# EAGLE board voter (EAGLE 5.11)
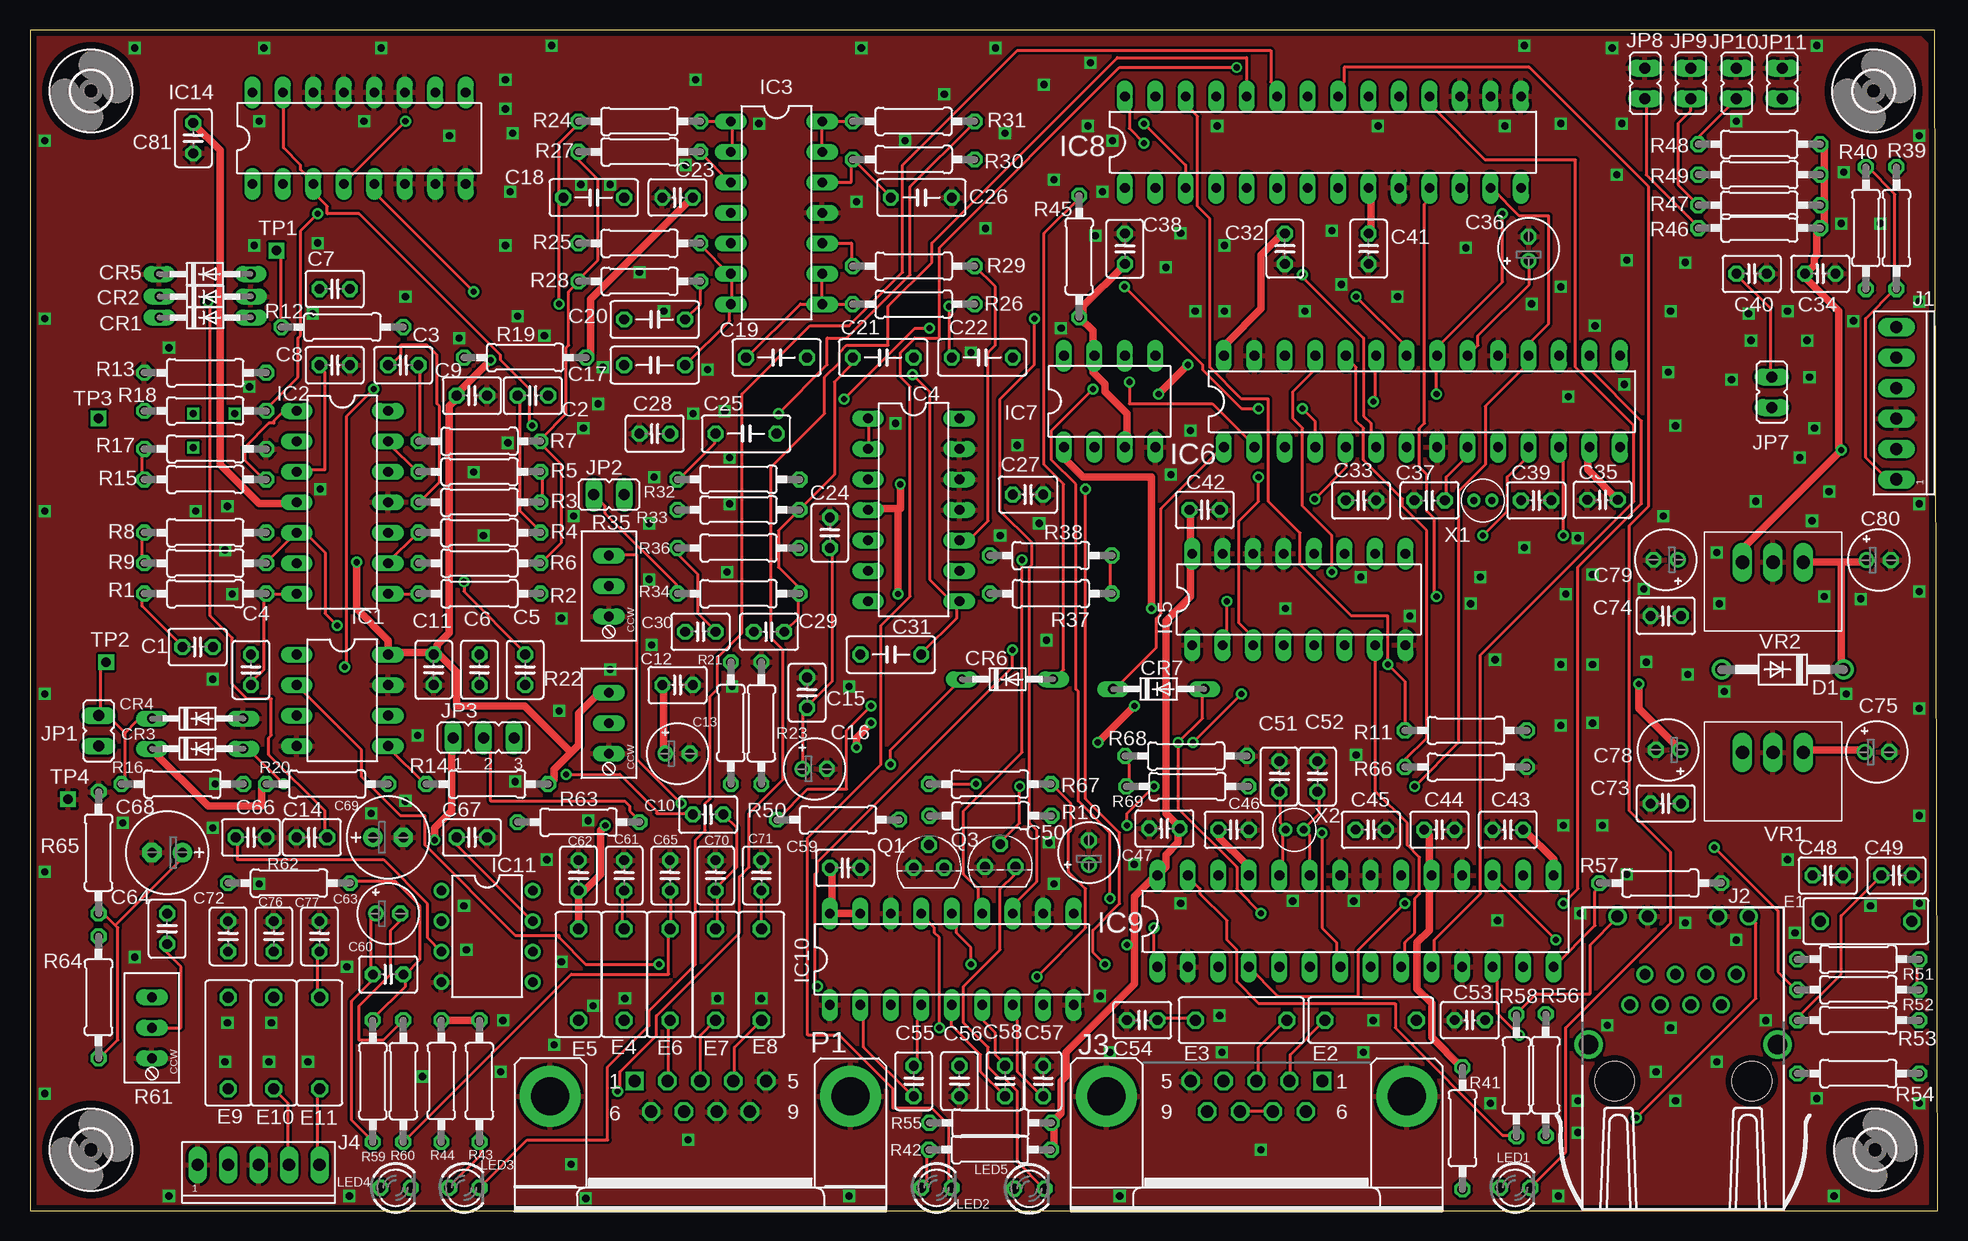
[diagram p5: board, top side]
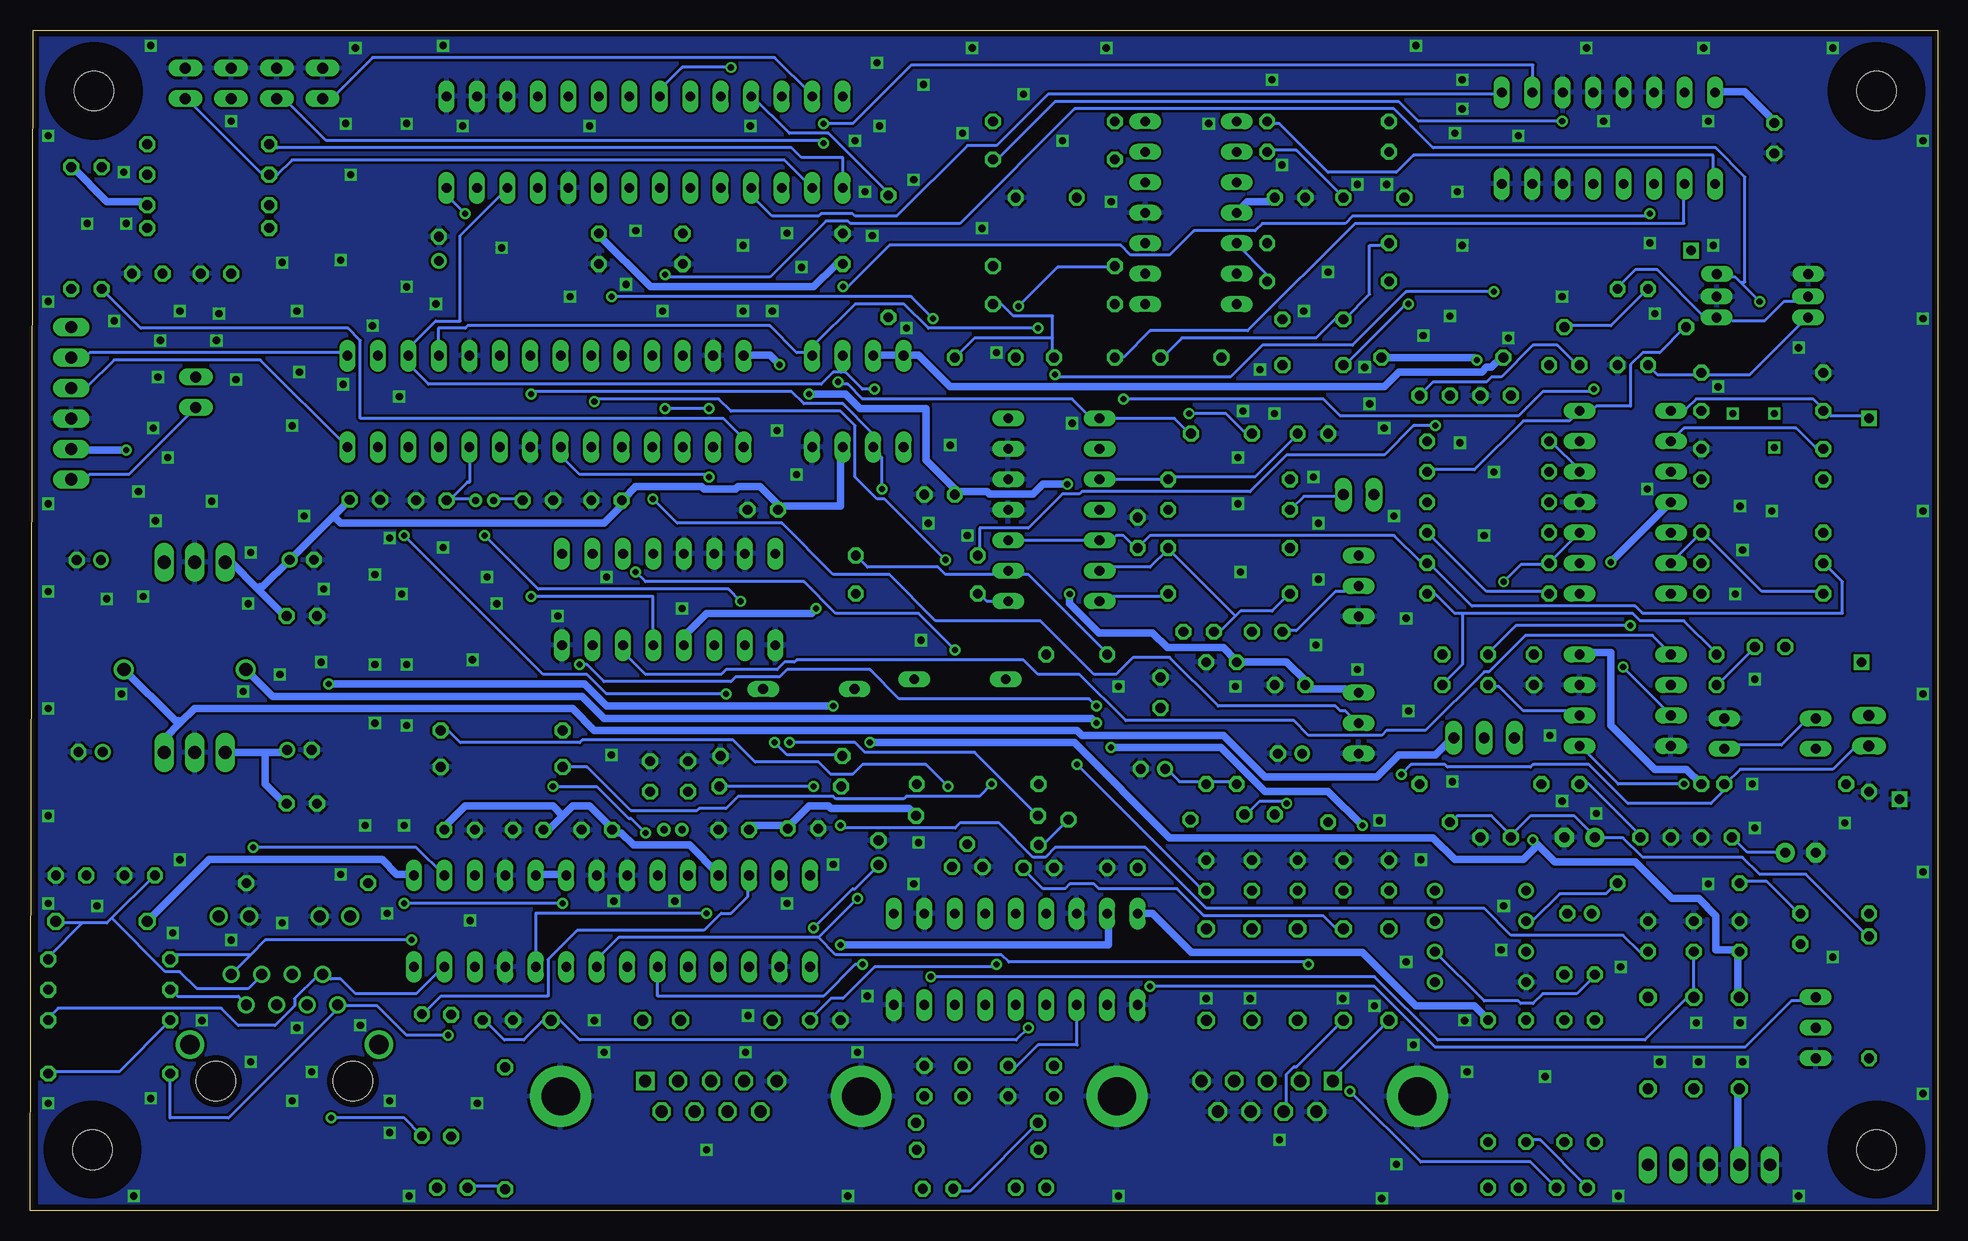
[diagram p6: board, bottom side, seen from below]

Size 159 x 98.44 mm. Coordinates in mm from the lower left corner, seen from the top.
Outline: 0,0.02 159,0 158.75,98.44 0,98.44 0,0.02
Copper layers (1*16): Top 0.035mm / dielectric 1.5mm / Bottom 0.035mm
Design rules "default *": minimum track width 10mil, minimum drill 20mil, track to track 8mil, track to pad 8mil, pad to pad 8mil, via to via 8mil, smd to smd 8mil, copper to edge 20mil, drill to drill 8mil, minimum pad ring 10mil, minimum via ring 8mil, stop-mask expansion 4mil, vias tented up to drill 0mil, thermal gap 10mil
Net classes: 0 default: width 0.203 mm, drill 0.508 mm, clearance 0.203 mm; 1 power: width 0.635 mm, drill 0.508 mm, clearance 0.203 mm

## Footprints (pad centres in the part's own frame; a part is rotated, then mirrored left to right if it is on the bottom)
C025-030X050 = drill 0.813 octagon: 1 -1.27,0; 2 1.27,0
E2-5 = drill 0.813 pad 1.27 round: + -1.016,0 | drill 0.813 pad 1.27 octagon: - 1.016,0
C050-030X075 = drill 0.813 octagon: 1 -2.54,0; 2 2.54,0
E2,5-7 = drill 0.813 pad 1.6 round: + -1.27,0 | drill 0.813 pad 1.6 octagon: - 1.27,0
DO34-7 = drill 0.813 long: A 3.81,0; C -3.81,0
DO41-10 = drill 1.118 round: A 5.08,0; C -5.08,0
FBONLEADSSMALL = drill 0.914 octagon: 1 -3.81,0; 2 3.81,0
DIL08 = drill 0.813 long: 1 -3.81,-3.81; 2 -1.27,-3.81; 3 1.27,-3.81; 4 3.81,-3.81; 5 3.81,3.81; 6 1.27,3.81; 7 -1.27,3.81; 8 -3.81,3.81
DIL14 = drill 0.813 long: 1 -7.62,-3.81; 2 -5.08,-3.81; 3 -2.54,-3.81; 4 0,-3.81; 5 2.54,-3.81; 6 5.08,-3.81; 7 7.62,-3.81; 8 7.62,3.81; 9 5.08,3.81; 10 2.54,3.81; 11 0,3.81; 12 -2.54,3.81; 13 -5.08,3.81; 14 -7.62,3.81
DIL16 = drill 0.813 long: 1 -8.89,-3.81; 2 -6.35,-3.81; 3 -3.81,-3.81; 4 -1.27,-3.81; 5 1.27,-3.81; 6 3.81,-3.81; 7 6.35,-3.81; 8 8.89,-3.81; 9 8.89,3.81; 10 6.35,3.81; 11 3.81,3.81; 12 1.27,3.81; 13 -1.27,3.81; 14 -3.81,3.81; 15 -6.35,3.81; 16 -8.89,3.81
DIL28-3 = drill 0.813 long: 1 -16.51,-2.54; 2 -13.97,-2.54; 3 -11.43,-2.54; 4 -8.89,-2.54; 5 -6.35,-2.54; 6 -3.81,-2.54; 7 -1.27,-2.54; 8 1.27,-2.54; 9 3.81,-2.54; 10 6.35,-2.54; 11 8.89,-2.54; 12 11.43,-2.54; 13 13.97,-2.54; 14 16.51,-2.54; 15 16.51,5.08; 16 13.97,5.08; 17 11.43,5.08; 18 8.89,5.08; 19 6.35,5.08; 20 3.81,5.08; 21 1.27,5.08; 22 -1.27,5.08; 23 -3.81,5.08; 24 -6.35,5.08; 25 -8.89,5.08; 26 -11.43,5.08; 27 -13.97,5.08; 28 -16.51,5.08
DIL28-3' = drill 0.813 long: 1 -16.51,-3.81; 2 -13.97,-3.81; 3 -11.43,-3.81; 4 -8.89,-3.81; 5 -6.35,-3.81; 6 -3.81,-3.81; 7 -1.27,-3.81; 8 1.27,-3.81; 9 3.81,-3.81; 10 6.35,-3.81; 11 8.89,-3.81; 12 11.43,-3.81; 13 13.97,-3.81; 14 16.51,-3.81; 15 16.51,3.81; 16 13.97,3.81; 17 11.43,3.81; 18 8.89,3.81; 19 6.35,3.81; 20 3.81,3.81; 21 1.27,3.81; 22 -1.27,3.81; 23 -3.81,3.81; 24 -6.35,3.81; 25 -8.89,3.81; 26 -11.43,3.81; 27 -13.97,3.81; 28 -16.51,3.81
DIL18 = drill 0.813 long: 1 -10.16,-3.81; 2 -7.62,-3.81; 3 -5.08,-3.81; 4 -2.54,-3.81; 5 0,-3.81; 6 2.54,-3.81; 7 5.08,-3.81; 8 7.62,-3.81; 9 10.16,-3.81; 10 10.16,3.81; 11 7.62,3.81; 12 5.08,3.81; 13 2.54,3.81; 14 0,3.81; 15 -2.54,3.81; 16 -5.08,3.81; 17 -7.62,3.81; 18 -10.16,3.81
DIL08' = drill 0.813 pad 1.27 round: 1 -3.81,-3.81; 2 -1.27,-3.81; 3 1.27,-3.81; 4 3.81,-3.81; 5 3.81,3.81; 6 1.27,3.81; 7 -1.27,3.81; 8 -3.81,3.81
MTA6-100 = drill 1.016 long: 1 5.08,0; 2 2.54,0; 3 0,0; 4 -2.54,0; 5 -5.08,0; 6 -7.62,0
J1 = drill 0.9 pad 1.3 round: 1 4.445,2.54; 2 3.175,0; 3 1.905,2.54; 4 0.635,0; 5 -0.635,2.54; 6 -1.905,0; 7 -3.175,2.54; 8 -4.445,0 | drill 1 pad 1.422 round: 9 5.465,7.37; 10 2.925,7.37; 11 -2.925,7.37; 12 -5.465,7.37 | drill 1.6 pad 2.184 round: M1 -7.875,-3.3; M2 7.875,-3.3 | hole 3.3: 5.715,-6.35; -5.715,-6.35
DSUB9F = drill 1.016 square: 1 -5.486,0 | drill 1.016 octagon: 2 -2.743,0; 3 0,0; 4 2.743,0; 5 5.486,0; 6 -4.115,2.54; 7 -1.372,2.54; 8 1.372,2.54; 9 4.115,2.54 | drill 3.175 pad 5.08 round: SHELL1 -12.522,1.27; SHELL2 12.522,1.27
MTA5-100 = drill 1.016 long: 1 5.08,0; 2 2.54,0; 3 0,0; 4 -2.54,0; 5 -5.08,0
JP1 = drill 0.914 long: 1 0,-1.27; 2 0,1.27
JP2 = drill 0.914 long: 1 -2.54,0; 2 0,0; 3 2.54,0
LED3MM = drill 0.813 octagon: A -1.27,0; K 1.27,0
DSUB9M = drill 1.016 square: 1 -5.486,0 | drill 1.016 octagon: 2 -2.743,0; 3 0,0; 4 2.743,0; 5 5.486,0; 6 -4.115,-2.54; 7 -1.372,-2.54; 8 1.372,-2.54; 9 4.115,-2.54 | drill 3.175 pad 5.08 round: G1 -12.522,-1.27; G2 12.522,-1.27
TO92 = drill 0.813 octagon: 1 1.27,0; 2 0,1.905; 3 -1.27,0
0207/10 = drill 0.813 octagon: 1 -5.08,0; 2 5.08,0
BOURNS3296 = drill 0.813 long: 1 2.54,0; 2 0,0; 3 -2.54,0
TESTPIN = drill 0.8 square: TP 0,0
3,3 = hole 3.3: 0,0
R-78XX = drill 1.092 long: 1 -2.54,0; 2 0,0; 3 2.54,0
TUNINGFORKXTAL = drill 0.6 round: 1 -0.75,0; 2 0.75,0

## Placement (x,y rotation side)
C1  47p  [C025-030X050]  13.97,47.01 0 top
C2  1000p  [C025-030X050]  41.91,67.96 0 top
C3  1000p  [C025-030X050]  31.11,70.5 0 top
C4  1000p  [C025-030X050]  18.41,45.11 90 top
C5  1000p  [C025-030X050]  41.27,45.11 90 top
C6  330p  [C025-030X050]  37.47,45.11 270 top
C7  0.1u  [C025-030X050]  25.4,76.85 0 top
C8  0.1u  [C025-030X050]  25.4,70.5 0 top
C9  0.1u  [C025-030X050]  36.83,67.96 0 top
C10  0.1u  [C025-030X050]  56.52,33.04 0 top
C11  0.1u  [C025-030X050]  33.66,45.11 270 top
C12  0.1u  [C025-030X050]  53.98,43.84 0 top
C13  22u  [E2-5]  53.98,38.12 0 top
C14  0.1u  [C025-030X050]  23.5,31.13 180 top
C15  0.1u  [C025-030X050]  64.77,43.2 90 top
C16  22u  [E2-5]  65.41,36.85 0 top
C17  0.068u  [C050-030X075]  52.07,70.5 180 top
C18  0.068u  [C050-030X075]  46.99,84.47 0 top
C19  0.068u  [C050-030X075]  62.23,71.14 0 top
C20  0.068u  [C050-030X075]  52.07,74.31 0 top
C21  0.068u  [C050-030X075]  71.12,71.14 0 top
C22  0.068u  [C050-030X075]  79.38,71.14 180 top
C23  0.1u  [C025-030X050]  53.98,84.47 180 top
C24  0.1u  [C025-030X050]  66.67,56.54 90 top
C25  0.015u  [C050-030X075]  59.69,64.79 0 top
C26  6800p  [C050-030X075]  74.3,84.47 0 top
C27  0.1u  [C025-030X050]  83.19,59.71 0 top
C28  1000p  [C025-030X050]  52.07,64.79 180 top
C29  22p  [C025-030X050]  61.59,48.28 180 top
C30  0.1u  [C025-030X050]  55.88,48.28 0 top
C31  4700p  [C050-030X075]  71.75,46.38 0 top
C32  0.1u  [C025-030X050]  104.6,80.21 270 top
C33  0.1u  [C025-030X050]  110.95,59.23 0 top
C34  0.1u  [C025-030X050]  149.22,78.12 0 top
C35  0.1u  [C025-030X050]  131.09,59.28 180 top
C36  10u  [E2-5]  124.92,80.21 90 top
C37  22p  [C025-030X050]  116.66,59.23 180 top
C38  0.1u  [C025-030X050]  91.26,80.21 90 top
C39  22p  [C025-030X050]  125.55,59.23 0 top
C40  0.22u  [C025-030X050]  143.51,78.12 0 top
C41  0.1u  [C025-030X050]  111.58,80.21 270 top
C42  0.1u  [C025-030X050]  97.92,58.44 0 top
C43  0.1u  [C025-030X050]  123.19,31.77 180 top
C44  0.1u  [C025-030X050]  117.47,31.77 0 top
C45  0.1u  [C025-030X050]  111.76,31.77 0 top
C46  0.1u  [C025-030X050]  100.33,31.77 0 top
C47  0.1u  [C025-030X050]  94.56,31.87 180 top
C48  0.1u  [C025-030X050]  149.86,27.96 0 top
C49  0.1u  [C025-030X050]  155.57,27.96 0 top
C50  10u  [E2-5]  88.27,29.86 90 top
C51  22p  [C025-030X050]  104.14,36.22 90 top
C52  22p  [C025-030X050]  107.31,36.22 90 top
C53  47p  [C025-030X050]  120.02,15.89 180 top
C54  47p  [C025-030X050]  92.71,15.89 180 top
C55  0.1u  [C025-030X050]  73.66,10.81 90 top
C56  0.1u  [C025-030X050]  77.47,10.81 270 top
C57  0.1u  [C025-030X050]  84.45,10.81 90 top
C58  0.1u  [C025-030X050]  81.28,10.81 90 top
C59  0.1u  [C025-030X050]  67.94,28.59 0 top
C60  47p  [C025-030X050]  29.84,19.7 0 top
C61  47p  [C025-030X050]  49.53,27.96 90 top
C62  47p  [C025-030X050]  45.72,27.96 90 top
C63  10u NP  [E2-5]  29.84,24.79 0 top
C64  0.47u  [C025-030X050]  11.43,23.52 270 top
C65  47p  [C025-030X050]  53.34,27.96 90 top
C66  0.1u  [C025-030X050]  18.41,31.13 0 top
C67  0.1u  [C025-030X050]  36.83,31.13 0 top
C68  100u  [E2,5-7]  11.43,29.86 180 top
C69  100u  [E2,5-7]  29.84,31.13 0 top
C70  47p  [C025-030X050]  57.15,27.96 90 top
C71  47p  [C025-030X050]  60.96,27.96 90 top
C72  47p  [C025-030X050]  16.51,22.88 90 top
C73  0.1u  [C025-030X050]  136.35,33.95 180 top
C74  0.1u  [C025-030X050]  136.35,49.6 180 top
C75  4.7u  [E2-5]  153.95,38.25 0 top
C76  47p  [C025-030X050]  20.32,22.88 90 top
C77  47p  [C025-030X050]  24.13,22.88 90 top
C78  1.0u  [E2-5]  136.55,38.42 180 top
C79  1.0u  [E2-5]  136.35,54.27 180 top
C80  4.7u  [E2-5]  154.1,54.25 0 top
C81  0.1u  [C025-030X050]  13.61,89.43 90 top
CR1  BAT85  [DO34-7]  14.61,74.47 0 top
CR2  BAT85  [DO34-7]  14.61,76.22 0 top
CR3  BAT85  [DO34-7]  13.97,38.53 0 top
CR4  BAT85  [DO34-7]  13.97,41.04 0 top
CR5  BAT85  [DO34-7]  14.58,78.1 0 top
CR6  BAT85  [DO34-7]  81.48,44.32 0 top
CR7  BAT85  [DO34-7]  94.08,43.5 0 top
D1  1N5819  [DO41-10]  146.1,45.13 180 top
E1  FBONLDSM  [FBONLEADSSMALL]  153.03,24.15 180 top
E2  FBONLDSM  [FBONLEADSSMALL]  111.76,15.89 180 top
E3  FBONLDSM  [FBONLEADSSMALL]  100.97,15.89 0 top
E4  FBONLDSM  [FBONLEADSSMALL]  49.53,19.7 90 top
E5  FBONLDSM  [FBONLEADSSMALL]  45.72,19.7 90 top
E6  FBONLDSM  [FBONLEADSSMALL]  53.34,19.7 90 top
E7  FBONLDSM  [FBONLEADSSMALL]  57.15,19.7 90 top
E8  FBONLDSM  [FBONLEADSSMALL]  60.96,19.7 90 top
E9  FBONLDSM  [FBONLEADSSMALL]  16.51,13.99 270 top
E10  FBONLDSM  [FBONLEADSSMALL]  20.32,13.99 270 top
E11  FBONLDSM  [FBONLEADSSMALL]  24.13,13.99 270 top
IC1  MCP4131  [DIL08]  26.04,42.57 270 top
IC2  MCP6004P  [DIL14]  26.04,59.08 270 top
IC3  MCP6004P  [DIL14]  62.23,83.2 270 top
IC4  MCP6004P  [DIL14]  73.66,58.44 270 top
IC5  74HC139N  [DIL16]  105.77,50.97 0 top
IC6  DSPIC33FJ128GP802  [DIL28-3]  116.03,66.21 0 top
IC7  25LC080  [DIL08]  89.99,67.48 0 top
IC8  MCP23S17SP  [DIL28-3']  107.77,89.1 0 top
IC9  ENC28J60SP  [DIL28-3']  110.49,24.15 0 top
IC10  MAX3222  [DIL18]  76.83,20.97 0 top
IC11  AD820AN  [DIL08']  38.1,22.88 270 top
IC14  74HC4053N  [DIL16]  27.43,89.43 0 top
J1  [MTA6-100]  155.57,66.06 270 top
J2  J1011F01P  [J1]  137.79,17.16 0 top
J3  DB9FRASFLUSH  [DSUB9F]  102.23,10.81 180 top
J4  [MTA5-100]  19.05,3.83 180 top
JP1  [JP1]  5.71,40.03 0 top
JP2  [JP1]  48.26,59.71 270 top
JP3  [JP2]  37.8,39.44 0 top
JP7  [JP1]  145.19,68.24 0 top
JP8  [JP1]  134.62,94 0 top
JP9  [JP1]  138.43,94 0 top
JP10  [JP1]  142.24,94 0 top
JP11  [JP1]  146.05,94 0 top
LED1  [LED3MM]  123.8,1.93 0 top
LED2  [LED3MM]  75.56,1.93 0 top
LED3  [LED3MM]  36.2,1.93 0 top
LED4  [LED3MM]  30.48,1.93 0 top
LED5  [LED3MM]  83.31,1.85 0 top
P1  DB9MRASFLUSH  [DSUB9M]  55.88,10.81 0 top
Q1  2N4401  [TO92]  74.93,28.59 0 top
Q3  2N4401  [TO92]  80.87,28.67 0 top
R1  220K  [0207/10]  14.61,51.46 0 top
R2  7.32K  [0207/10]  37.47,51.46 180 top
R3  3.01K  [0207/10]  37.47,59.08 0 top
R4  1K  [0207/10]  37.47,56.54 0 top
R5  1K  [0207/10]  37.47,61.62 0 top
R6  17.8K  [0207/10]  37.47,54 180 top
R7  154K  [0207/10]  37.47,64.16 180 top
R8  10K  [0207/10]  14.61,56.54 0 top
R9  220K  [0207/10]  14.61,54 0 top
R10  10K  [0207/10]  80.06,32.94 0 top
R11  4.7K  [0207/10]  119.68,40.05 180 top
R12  220  [0207/10]  26.04,73.68 0 top
R13  22K  [0207/10]  14.61,69.87 0 top
R14  100K  [0207/10]  38.1,35.58 0 top
R15  33K  [0207/10]  14.61,60.98 0 top
R16  100K  [0207/10]  12.7,35.58 0 top
R17  10K  [0207/10]  14.61,63.52 0 top
R18  220  [0207/10]  14.61,66.69 0 top
R19  4.7  [0207/10]  41.27,71.14 0 top
R20  10K  [0207/10]  24.77,35.58 180 top
R21  2.2K  [0207/10]  58.42,40.66 90 top
R22  10K  [BOURNS3296]  48.26,40.66 270 top
R23  2.2K  [0207/10]  60.96,40.66 270 top
R24  3.01K  [0207/10]  50.8,90.83 0 top
R25  8.25K  [0207/10]  50.8,80.66 0 top
R26  11.0K  [0207/10]  73.66,75.58 180 top
R27  47.5K  [0207/10]  50.8,88.28 0 top
R28  16.2K  [0207/10]  50.8,77.49 0 top
R29  12.1K  [0207/10]  73.66,78.76 180 top
R30  12,4K  [0207/10]  73.66,87.65 180 top
R31  7.68K  [0207/10]  73.66,90.83 0 top
R32  21.5K  [0207/10]  59.05,60.98 0 top
R33  110K  [0207/10]  59.05,58.44 0 top
R34  1.0M  [0207/10]  59.05,51.46 0 top
R35  100K  [BOURNS3296]  48.26,52.09 270 top
R36  100K  [0207/10]  59.05,55.27 0 top
R37  100K  [0207/10]  85.09,51.46 180 top
R38  33K  [0207/10]  85.09,54.63 0 top
R39  10K  [0207/10]  155.57,81.94 90 top
R40  360  [0207/10]  153.03,81.94 90 top
R41  180  [0207/10]  119.41,6.88 90 top
R42  180  [0207/10]  80.01,5.1 0 top
R43  180  [0207/10]  37.47,10.81 90 top
R44  180  [0207/10]  34.29,10.81 90 top
R45  10K  [0207/10]  87.45,79.57 270 top
R46  10K  [0207/10]  144.15,81.94 0 top
R47  10K  [0207/10]  144.15,83.84 0 top
R48  10K  [0207/10]  144.15,88.92 0 top
R49  10K  [0207/10]  144.15,86.38 0 top
R50  4.7K  [0207/10]  67.36,32.61 0 top
R51  49.9  [0207/10]  152.4,20.97 180 top
R52  49.9  [0207/10]  152.4,18.43 0 top
R53  49.9  [0207/10]  152.4,15.89 0 top
R54  49.9  [0207/10]  152.4,11.45 0 top
R55  180  [0207/10]  80.06,7.34 0 top
R56  180  [0207/10]  126.34,11.32 270 top
R57  2.32K  [0207/10]  135.89,27.32 180 top
R58  180  [0207/10]  123.9,11.27 90 top
R59  330K  [0207/10]  28.57,10.81 270 top
R60  33  [0207/10]  31.11,10.81 270 top
R61  10K  [BOURNS3296]  10.16,15.26 270 top
R62  10K  [0207/10]  21.59,27.32 0 top
R63  4.7  [0207/10]  45.72,32.41 0 top
R64  10K  [0207/10]  5.71,17.8 90 top
R65  10K  [0207/10]  5.71,29.86 270 top
R66  10K  [0207/10]  119.68,37 180 top
R67  4.7K  [0207/10]  80.01,35.58 0 top
R68  10K  [0207/10]  96.37,37.92 180 top
R69  4.7K  [0207/10]  96.47,35.38 0 top
TP1  TESTPINTPSQ025  [TESTPIN]  20.55,80.06 0 top
TP2  TESTPINTPSQ025  [TESTPIN]  6.35,45.74 0 top
TP3  TESTPINTPSQ025  [TESTPIN]  5.71,66.06 0 top
TP4  TESTPINTPSQ025  [TESTPIN]  3.17,34.31 0 top
U$21  [3,3]  5.08,93.36 0 top
U$22  [3,3]  5.08,5.1 0 top
U$23  [3,3]  153.8,5.1 0 top
U$24  [3,3]  153.67,93.36 0 top
VR1  R785_0-0_5  [R-78XX]  145.29,38.22 180 top
VR2  R783_3-0_5  [R-78XX]  145.29,54.07 180 top
X1  9.60MHz  [TUNINGFORKXTAL]  121.11,59.23 180 top
X2  25.0MHz  [TUNINGFORKXTAL]  105.41,31.77 0 top

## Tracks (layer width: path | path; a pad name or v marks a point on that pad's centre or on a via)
!CS_EEPROM  (via drill 0.51)
  Top 0.635: v93.47,50.21 93.47,61.18 87.78,61.18 86.36,62.61 86.36,63.62 IC7.1
  Bottom 0.635: v93.47,50.21 93.88,49.8 102.62,49.8 104.44,47.98 104.44,47.16 IC5.4
!CS_ETHER
  Top 0.254: IC9.9 114.4,20.34 114.61,20.54 114.61,22.37 115.42,23.18 115.42,26.03 115.82,26.44 115.82,29.48 114.81,30.5 114.81,32.33 112.17,34.97 112.17,47.16 IC5.7
!CS_IOEXP  (via drill 0.51)
  Top 0.254: v117.25,51.23 117.04,51.43 117.04,57.73 116.43,58.34 116.43,61.39 115.82,62 115.82,65.25 116.23,65.65 116.23,83.94 116.64,84.35 116.64,85.16 IC8.11
  Bottom 0.254: v117.25,51.23 107.09,51.23 107.09,47.16 IC5.5
!CS_POT
  Bottom 0.254: IC1.1 22.35,46.55 23.77,47.98 34.34,47.98 37.39,44.93 37.8,44.93 42.67,40.05 45.92,40.05 46.33,39.64 52.43,39.64 53.65,40.86 67.67,40.86 71.53,44.72 74.98,44.72 76.2,45.94 95.1,45.94 95.3,45.74 96.11,45.74 96.72,45.13 100.99,45.13 101.4,44.72 107.7,44.72 109.53,46.55 109.53,47.16 IC5.6
!CTCSS_IN  (via drill 0.51)
  Top 0.254: E8.2 C71.1 | v71.73,37.21 71.73,38.43 77.62,44.32 CR6.C
  Bottom 0.254: v71.73,37.21 61.37,26.84 60.96,26.84 C71.1
!INT_ETHER  (via drill 0.51)
  Top 0.254: IC9.4 104.04,17.9 110.74,17.9 110.74,21.76 v114.61,25.62 | v127.81,25.62 129.03,26.84 129.03,53.67 134.31,58.95 134.31,65.86 130.05,70.12 130.05,71.14 IC6.16
  Bottom 0.254: v114.61,25.62 v127.81,25.62
!MCLR
  Top 0.254: CR7.C 90.42,43.51 93.88,46.96 93.88,49.4 94.28,49.8 94.28,58.54 99.36,63.62 IC6.1
  Bottom 0.254: R40.1 149.76,73.58 132.49,73.58 131.47,72.56 131.47,66.06 101.19,66.06 99.57,64.43 99.57,63.83 IC6.1
!POT_CS  (via drill 0.51)
  Top 0.254: v99.77,50.82 99.77,47.37 99.57,47.16 IC5.2 | v121.11,56.31 123.14,58.34 123.14,61.18 124.77,62.81 124.77,63.62 IC6.11
  Bottom 0.254: v99.77,50.82 100.79,51.84 116.64,51.84 v121.11,56.31
!PRST
  Top 0.254: R40.2 153.21,86.99 155.45,84.75 155.45,77.03 R39.1 155.45,76.83 153.01,74.39 153.01,62.81 154.84,60.98 J1.1
  Bottom 0.254: JP7.1 150.77,61.39 154.03,61.39 154.43,60.98 J1.1
!RST  (via drill 0.51)
  Top 0.254: CR7.A 97.74,43.51 97.74,41.07 v95.71,39.03 95.71,33.55 100.58,28.67 100.58,26.84 v102.62,24.81 | IC9.10 117.04,20.54 117.04,22.57 120.9,26.44 120.9,46.35 133.71,59.15 133.71,65.45 128.83,70.33 128.83,87.6 121.31,87.6 117.04,91.87 117.04,92.68 116.84,92.88 IC8.18
  Bottom 0.254: R10.1 80.26,38.22 89.41,38.22 90.22,39.03 v95.71,39.03 | IC9.10 116.84,24.81 v102.62,24.81
+3.3V  (via drill 0.51)
  Top 0.635: 72.34,58.54 72.54,58.54 v72.54,60.57 | 72.34,58.54 69.9,58.54 IC4.4 | IC6.28 99.77,71.55 99.77,72.36 102.62,75.2 102.62,79.67 104.44,81.5 C32.1 | v94.08,68.09 v96.52,70.53 | v38.41,70.94 35.56,68.09 C9.1 35.56,67.69 34.95,67.08 34.95,48.18 33.93,47.16 33.93,46.96 C11.1 | C23.1 55.07,84.35 46.74,76.02 46.74,71.55 46.53,71.34 46.53,71.14 R19.2 | 45.11,38.22 45.72,38.83 45.72,41.47 47.35,43.1 48.16,43.1 R22.3 | 45.11,38.22 43.69,36.8 43.69,35.99 43.28,35.58 R14.2 | C13.+ 52.83,38.22 52.83,43.71 C12.1 | CR3.C 10.16,38.43 14.83,33.75 19.3,33.75 19.3,35.17 19.51,35.38 19.51,35.58 R20.2 | C11.1 33.53,46.55 29.87,46.55 IC1.8 29.87,46.76 29.87,47.57 27.23,50.21 v27.23,54.07 | C81.2 13.61,90.65 15.85,88.41 15.85,62.2 19.1,58.95 22.15,58.95 IC2.4 | 45.11,38.22 41.25,42.08 35.56,42.08 35.56,44.93 33.73,46.76 C11.1 | v72.34,51.43 72.34,58.54
  Bottom 0.635: v72.54,60.57 74.57,60.57 75.39,59.76 79.05,59.76 79.25,59.96 81.69,59.96 81.89,59.76 C27.1 81.89,60.17 84.33,62.61 84.33,66.87 89.81,66.87 91.03,68.09 v94.08,68.09 | v96.52,70.53 97.33,71.34 99.36,71.34 IC6.28 | IC3.4 58.32,83.33 57.51,84.14 55.68,84.14 55.47,84.35 55.27,84.35 C23.1 | v38.41,70.94 38.61,71.14 R19.2 | R22.3 48.36,43.3 49.17,43.3 49.38,43.51 52.43,43.51 52.63,43.71 C12.1 52.63,44.11 54.25,45.74 R21.2 58.52,45.94 59.54,46.96 64.21,46.96 65.43,48.18 69.9,48.18 72.34,50.62 v72.34,51.43 | C81.2 13.61,90.85 16.05,93.29 18.49,93.29 IC14.16 | v27.23,54.07 IC2.4 | R20.2 19.71,35.58 20.93,36.8 23.57,36.8 27.23,40.46 27.23,46.55 29.67,46.55 IC1.8
ASEL1  (via drill 0.51)
  Top 0.254: v92.86,90.65 96.32,87.19 96.32,85.36 IC8.3
  Bottom 0.254: v92.86,90.65 90.42,90.65 85.55,95.52 33.73,95.52 33.73,93.29 IC14.10
ASEL2
  Bottom 0.254: IC14.9 36.37,93.09 74.17,93.09 78.44,88.82 80.87,88.82 86.77,82.93 90.22,82.93 90.42,83.13 93.07,83.13 93.27,82.93 97.13,82.93 98.75,84.55 98.75,85.16 IC8.4
DAC  (via drill 0.51)
  Top 0.254: v65.63,18.71 65.43,18.92 65.43,28.06 65.63,28.27 65.63,29.08 81.89,45.33 v81.89,46.76 | v108.51,53.26 108.51,56.31 106.07,58.75 106.07,65.25 105.26,66.06 105.26,68.3 107.09,70.12 107.09,71.14 IC6.25
  Bottom 0.254: v65.63,18.71 46.94,18.71 41.86,13.63 16.05,13.63 12.19,17.5 10.36,17.5 10.16,17.7 R61.3 | v81.89,46.76 84.94,49.8 91.85,49.8 94.49,52.45 107.7,52.45 v108.51,53.26
FLTNOISE
  Top 0.254: TP1.TP 20.93,79.67 20.93,73.78 R12.1 | R3.2 42.67,59.15 42.67,61.59 R5.2
  Bottom 0.254: R5.2 42.47,61.79 38.61,61.79 34.54,65.86 30.68,65.86 IC2.14 29.67,66.67 28.85,66.67 28.45,67.08 25.6,67.08 25.6,70.53 24.59,71.55 23.16,71.55 21.13,73.58 R12.1
GND  (via drill 0.6)
  other vias: 157.48,32.94 157.48,41.88 1.22,89.22 1.22,74.39 1.22,9.77 1.22,28.26 1.22,58.34 1.22,43.1 11.58,1.24 26.62,1.24 46.33,1.04 68.28,1.24 90.83,1.24 111.96,15.87 127.41,1.24 150.37,1.24 157.48,8.96 157.48,25.62 157.48,51.63 157.48,58.95 157.48,75.81 157.48,89.63 148.95,97.15 131.88,96.95 124.56,97.15 88.39,95.73 80.47,96.95 84.53,93.9 69.29,96.95 43.48,97.15 29.26,96.95 19.51,96.95 8.74,96.95 19.1,90.85 34.95,89.63 39.62,91.87 39.62,94.3 40.03,84.96 39.62,80.49 31.29,76.22 40.64,74.59 35.76,72.77 18.29,68.7 7.72,32.33 24.18,60.17 15.24,31.92 32.31,39.64 31.29,34.16 36.17,25.42 36.37,21.76 26.42,20.34 19.1,27.25 16.46,15.67 20.12,15.67 23.16,12.42 19.91,12.42 16.26,12.42 39.42,15.87 32.72,11.2 8.74,21.15 49.58,17.7 57.3,17.7 43.08,29.28 46.53,32.53 44.09,41.68 40.44,35.78 44.3,49.4 37.8,56.31 45.31,57.93 36.98,61.59 39.83,64.03 46.13,65.25 47.35,67.28 52.02,61.18 51.61,57.32 58.32,58.95 58.32,62.81 57.91,66.67 56.49,70.12 47.75,70.33 42.88,72.97 50.8,78.25 48.36,85.57 45.92,85.57 55.47,94.3 60.76,90.65 54.66,87.19 68.88,84.14 79.65,81.91 72.95,89.22 76.2,93.09 81.28,89.83 78.44,71.55 85.95,73.58 131.47,15.46 72.14,65.65 82.3,63.82 122.33,24.2 127.81,32.13 131.06,32.13 135.53,11.6 137.16,9.16 129.03,9.16 129.03,6.52 121.72,8.96 140.61,12.42 148.95,9.37 144.68,15.87 147.12,23.18 153.42,25.42 133.1,28.06 146.51,29.28 130.25,40.66 127.61,40.46 130.25,45.54 127.61,45.54 134.72,45.74 138.18,44.72 141.22,43.3 151.38,43.1 152.6,51.02 149.56,51.23 140.82,50.62 140.61,54.88 148.54,57.53 143.87,59.15 141.83,69.31 148.34,69.51 148.13,72.56 143.46,72.56 143.26,74.8 146.51,75 151.99,74.19 150.98,82.32 154.23,82.32 151.18,86.58 137.97,79.06 133.1,79.27 132.28,86.38 132.69,90.65 142.24,90.85 119.68,80.28 108.51,81.71 114,76.22 127.61,77.03 125.17,75.61 106.27,75 109.32,77.24 122.94,90.44 112.37,90.44 98.96,90.44 90.22,89.22 85.34,85.97 94.69,78.66 95.91,81.5 99.57,80.49 99.57,75 97.13,75 88.8,81.3 96.72,65.04 84.12,57.32 80.87,56.31 110.95,52.85 120.9,52.85 130.45,73.78 128.22,67.89 132.89,68.9 124.56,55.29 128.02,51.43 130.25,53.06 122.12,45.94 120.09,50.62 115.01,49.6 104.65,50.21 110.54,38.02 95.91,25.62 110.34,25.83 105.26,25.83 84.73,47.57 84.94,30.7 92.05,28.87 89.2,17.9 99.16,16.28 99.36,13.23 111.15,13.23 90.02,13.23 102.62,5.1 54.86,5.91 60.96,17.7 15.24,44.32 16.87,51.43 16.26,55.09 13.82,58.34 16.46,58.74 11.58,71.95 18.69,80.49 23.98,80.69 23.57,74.8 27.84,90.85 40.23,89.83 51.61,52.65 51.82,47.16 58.52,43.71 48.36,45.13 68.28,43.71 58.12,53.26 44.3,20.75 46.94,17.09 43.69,13.84 39.22,11.6 45.11,3.88 85.34,27.25 136.55,69.92 136.75,75 137.16,65.45 129.03,56.1 142.24,22.58 136.14,57.93 134.52,51.84 147.52,62.81 148.74,65.25 149.96,59.96 127.61,90.65 89.41,84.96 88.19,90.44 95.1,61.39 55.27,66.47 52.83,75 15.44,35.58 28.45,33.14 136.75,15.26 137.97,24 129.24,24.81
  pour Top: 0.64,97.81 0.64,0.66 158.12,0.66 158.12,97.17 157.48,97.81
  pour Bottom: 0.64,97.81 0.64,0.66 158.12,0.66 158.12,97.81
GPS_PPS  (via drill 0.51)
  Top 0.254: R69.1 91.44,35.38 91.64,35.58 91.64,37.21 91.44,37.41 91.44,37.82 R68.2 | v127.81,56.31 127.81,63.42 127.61,63.62 IC6.12 | v96.93,39.03 v100.99,43.1
  Bottom 0.254: v127.81,56.31 116.23,44.72 112.57,44.72 110.95,43.1 v100.99,43.1 | v96.93,39.03 95.91,38.02 91.44,38.02 R68.2
GPS_RX  (via drill 0.51)
  Top 0.254: R67.1 v78.84,35.58 | R66.2 114.61,37.61 116.43,39.44 116.43,56.71 114.4,58.75 114.4,59.35 111.15,62.61 111.15,65.25 110.54,65.86 110.54,70.33 109.73,71.14 IC6.24
  Bottom 0.254: v78.84,35.58 79.86,34.56 85.95,34.56 86.16,34.36 91.85,34.36 92.05,34.56 99.97,34.56 100.99,33.55 103.23,33.55 103.43,33.35 108.92,33.35 112.57,37 R66.2
ICSPCLK
  Bottom 0.254: IC6.15 132.69,71.34 132.89,71.55 154.03,71.55 154.43,71.14 J1.5
ICSPDAT
  Bottom 0.254: IC6.14 139.8,70.94 151.99,70.94 154.23,68.7 155.45,68.7 J1.4
N$1
  Top 0.254: R15.1 9.35,60.98 9.35,63.42 R17.1
  Bottom 0.254: IC2.2 21.13,65.25 11.79,65.25 10.16,63.62 9.55,63.62 R17.1
N$2
  Top 0.254: R58.2 123.95,16.48 125.58,18.11 130.05,18.11 130.05,22.17 132.28,24.4 J2.12
N$3
  Top 0.254: IC2.7 22.15,51.43 19.71,51.43 R1.2 19.51,51.43 19.51,45.13 18.49,44.11 18.49,43.91 C4.1
  Bottom 0.254: C1.2 15.24,46.96 18.29,43.91 C4.1
N$4
  Bottom 0.254: 39.62,49.8 40.23,49.8 41.86,51.43 42.47,51.43 R2.1 | 39.62,49.8 25.4,49.8 24.79,49.19 21.13,49.19 18.49,46.55 C4.2 | 39.62,49.8 39.62,45.54 41.25,43.91 C5.1
N$5  (via drill 0.51)
  Top 0.254: v36.17,52.45 36.17,51.63 41.25,46.55 C5.2
  Bottom 0.254: IC2.10 R6.2 32.51,53.87 34.75,53.87 v36.17,52.45
N$6
  Top 0.254: IC2.8 29.87,51.43 32.31,51.43 R2.2 | C2.1 40.64,67.89 40.84,67.69 40.84,58.34 42.47,56.71 R4.2
  Bottom 0.254: R4.2 42.47,56.51 37.59,51.63 32.51,51.63 R2.2
N$7
  Top 0.254: R3.1 32.51,59.15 34.14,60.78 34.14,67.08 33.93,67.28 33.93,71.34 33.12,72.16 30.89,72.16 30.89,71.34 29.87,70.33 C3.1
  Bottom 0.254: C2.2 43.08,68.09 42.06,69.11 37.59,69.11 37.19,69.51 36.37,69.51 33.73,72.16 31.7,72.16 30.07,70.53 29.87,70.53 C3.1
N$8
  Top 0.254: C3.2 32.51,70.33 32.51,64.23 R7.2
  Bottom 0.254: IC2.12 29.87,61.79 32.11,64.03 32.31,64.03 R7.2
N$9
  Top 0.254: IC2.3 22.35,61.79 24.59,61.79 24.59,69.92 24.18,70.33 C8.1
  Bottom 0.254: CR1.C 10.97,74.39 15.65,69.72 19.51,69.72 R13.2 19.71,69.72 23.37,69.72 23.98,70.33 C8.1
N$10
  Top 0.254: C1.1 12.6,47.16 9.35,50.41 9.35,51.43 R1.1
  Bottom 0.254: IC2.6 R8.2 19.51,56.51 14.63,51.63 9.55,51.63 R1.1
N$11
  Bottom 0.254: CR2.C 10.97,76.22 11.38,75.81 12.8,75.81 14.43,74.19 17.07,74.19 17.27,74.39 18.29,74.39 CR1.A 18.49,74.59 19.51,74.59 23.37,78.45 25.2,78.45 26.62,77.03 C7.2
N$12
  Top 0.254: IC2.13 29.87,64.03 32.31,61.59 R5.1
N$13
  Top 0.254: IC2.9 29.87,54.07 32.31,56.51 R4.1
N$14  (via drill 0.51)
  Top 0.254: 5.89,41.88 5.89,41.47 JP1.2 5.89,41.88 | 5.89,41.88 5.89,45.33 6.3,45.74 TP2.TP | 7.92,39.85 7.92,35.78 7.72,35.58 R16.1 | 7.92,39.85 5.89,41.88 | IC1.5 29.87,38.63 32.92,35.58 R14.1 | v21.13,35.58 18.29,38.43 17.88,38.43 CR3.A | 7.92,39.85 8.94,40.86 10.16,40.86 CR4.C
  Bottom 0.254: CR3.A 17.48,38.83 13.01,38.83 10.97,40.86 10.16,40.86 CR4.C | v21.13,35.58 26.62,35.58 29.67,38.63 IC1.5
N$15  (via drill 0.51)
  Top 0.254: v44.7,36.39 49.17,36.39 52.22,33.35 52.22,33.14 55.07,33.14 C10.1
  Bottom 0.254: JP1.1 5.89,38.63 6.91,38.63 8.74,36.8 16.46,36.8 17.68,35.58 R16.2 17.88,35.58 17.88,34.97 18.9,33.95 25.81,33.95 29.06,37.21 33.73,37.21 33.93,37 40.84,37 41.05,37.21 43.89,37.21 v44.7,36.39
N$16
  Bottom 0.254: C7.1 24.18,76.83 27.23,73.78 31.09,73.78 R12.2
N$17
  Bottom 0.254: IC4.3 R32.2 64.01,60.98 63.8,61.18 56.9,61.18 53.44,64.64 C28.1
N$18
  Top 0.254: R15.2 19.51,60.98 17.88,62.61 17.88,63.62 19.91,65.65 20.32,65.65 20.32,65.86 21.13,66.67 22.15,66.67 IC2.1
  Bottom 0.254: TP3.TP 5.89,66.06 6.1,66.26 8.94,66.26 9.35,66.67 R18.1 9.55,66.87 10.36,67.69 20.12,67.69 20.93,66.87 22.15,66.87 IC2.1
N$19
  Bottom 0.254: IC1.6 29.87,41.47 30.07,41.68 34.54,41.68 36.58,43.71 37.39,43.71 C6.2
N$20
  Bottom 0.635: E9.2 16.66,10.18 16.66,3.88 J4.2
N$21
  Top 0.254: C49.1 154.23,27.86 150.98,24.61 150.98,19.73 147.32,16.07 R53.1
  Bottom 0.254: R53.1 147.32,15.87 151.59,11.6 157.48,11.6 R54.2
N$22  (via drill 0.51)
  Top 0.254: v133.91,7.74 143.87,17.7 143.87,24 143.46,24.4 J2.9
  Bottom 0.254: v133.91,7.74 127.81,7.74 126.39,6.32 R56.2
N$23  (via drill 0.51)
  Top 0.254: R9.2 19.71,54.07 22.15,56.51 IC2.5 22.35,56.51 22.96,56.51 24.59,54.88 24.59,49.8 v25.6,48.79
  Bottom 0.254: v25.6,48.79 35.15,48.79 37.39,46.55 C6.1
N$24
  Top 0.254: IC3.2 58.52,88.41 58.52,90.65 IC3.1 58.32,90.85 55.88,90.85 R24.2
  Bottom 0.254: IC14.1 18.69,85.77 18.69,88.01 43.69,88.01 45.11,86.58 50.8,86.58 54.86,90.65 55.88,90.65 R24.2
N$25
  Top 0.254: IC3.13 IC3.14 66.04,90.85 68.48,90.85 R31.1
N$26  (via drill 0.51)
  Top 0.254: R32.1 54.05,60.98 57.1,64.03 57.1,64.64 C25.1 | v62.38,66.47 66.45,70.53 66.45,72.77 68.07,72.77 73.36,78.05 73.36,85.36 78.64,90.65 R31.2
  Bottom 0.254: v62.38,66.47 59.33,66.47 57.71,64.84 57.3,64.84 C25.1
N$27
  Top 0.254: C55.1 73.56,9.57 69.49,13.63 69.49,16.89 IC10.2
N$28  (via drill 0.51)
  Top 0.254: v127.2,22.57 121.92,27.86 IC9.17
  Bottom 0.254: v127.2,22.57 139.4,22.57 140.61,21.36 | 140.61,21.36 142.24,19.73 J2.1 | 140.61,21.36 147.12,21.36 147.32,21.15 R51.2
N$29
  Bottom 0.254: R35.2 48.36,52.04 48.77,51.63 50.19,51.63 53.44,48.38 54.46,48.38 C30.1
N$30
  Top 0.254: IC3.12 66.04,85.77 68.48,85.77 68.48,87.6 R30.2 68.68,87.6 71.73,84.55 C26.1
N$31
  Top 0.254: C30.2 57.1,48.38 55.68,49.8 55.68,53.05 54.05,54.68 54.05,55.09 R36.1
N$32
  Top 0.254: JP2.1 47.95,58.75 47.95,58.14 53.85,52.24 53.85,51.63 R34.1
  Bottom 0.254: 58.52,49.6 59.74,48.38 60.15,48.38 C29.2 | 58.52,49.6 58.12,50.01 55.47,50.01 54.05,51.43 R34.1 | 58.52,49.6 64.01,55.09 R36.2 64.21,55.09 65.63,53.67 69.49,53.67 69.7,53.46 IC4.6
N$33
  Top 0.254: IC6.9 119.69,63.62 119.48,63.42 119.48,62.61 118.06,61.18 118.06,59.35 C37.1
  Bottom 0.254: X1.2 120.29,59.35 118.06,59.35 C37.1
N$34
  Bottom 0.254: R33.1 53.85,58.54 52.83,59.56 49.58,59.56 JP2.2
N$35
  Top 0.254: R37.1 90.02,51.63 90.02,54.48 R38.2
  Bottom 0.254: 77.22,53.05 75.79,53.05 69.29,46.55 C31.1 | 77.22,53.05 77.42,53.26 IC4.9 77.22,53.05 | 77.22,53.05 82.7,53.05 83.31,53.67 89.2,53.67 R38.2
N$36
  Top 0.254: C29.1 62.99,48.38 64.01,49.4 64.01,51.43 R34.2 64.01,51.63 64.01,52.04 62.38,53.67 62.38,56.71 64.01,58.34 R33.2 64.21,58.54 67.06,61.39 67.06,69.11 68.48,70.53 68.48,71.14 C21.1
  Bottom 0.254: IC4.7 69.7,50.82 69.29,51.23 64.41,51.23 64.21,51.43 R34.2 | IC14.2 21.13,85.57 21.13,82.32 48.56,82.32 57.51,73.38 65.63,73.38 67.87,71.14 C21.1
N$37
  Bottom 0.254: 123.95,59.35 124.16,59.35 C39.1 123.95,59.35 | 123.95,59.35 121.92,59.35 X1.1 | 123.95,59.35 122.53,60.78 122.33,60.78 122.33,63.62 IC6.10
N$38
  Top 0.254: IC6.20 120.7,72.16 120.7,72.97 124.97,77.24 124.97,79.06 C36.+
N$39  (via drill 0.51)
  Top 0.254: v102.41,61.18 102.41,59.15 100.79,57.53 100.79,48.99 101.6,48.18 101.6,47.37 101.8,47.16 IC5.3
  Bottom 0.254: v102.41,61.18 102.62,61.39 113.18,61.39 114.61,62.81 114.61,63.62 IC6.7
N$40
  Bottom 0.254: R50.2 72.54,32.53 74.57,30.5 Q1.2
N$41  (via drill 0.51)
  Top 0.254: v70.1,42.08 68.07,40.05 68.07,35.17 64.82,35.17 62.38,32.74 R50.1 | R11.2 114.61,44.11 v113.18,45.54 113.18,49.6 110.13,49.6 105.87,53.87 105.87,56.51 103.23,59.15 103.23,67.69 100.99,67.69 98.35,70.33 98.35,82.72 97.33,83.74 97.33,91.26 96.72,91.87 96.72,92.68 96.52,92.88 IC8.26
  Bottom 0.254: v70.1,42.08 70.71,42.69 86.56,42.69 89,45.13 95.91,45.13 96.52,44.52 100.18,44.52 100.58,44.11 111.15,44.11 112.57,45.54 v113.18,45.54
N$42
  Top 0.254: LED1.K 125.17,2.05 128.02,4.9 128.02,15.26 136.75,24 136.75,29.89 133.3,33.35 133.3,57.12 134.93,58.75 134.93,85.36 124.97,95.32 109.53,95.32 109.53,94.1 109.12,93.69 109.12,93.09 IC8.21
N$43  (via drill 0.51)
  Top 0.254: v100.58,95.32 90.83,95.32 75.79,80.28 75.79,72.77 73.76,72.77 72.54,71.55 72.54,69.51 73.36,68.7 73.36,51.23 70.92,48.79 70.92,37.21 64.82,31.11 64.82,14.65 67.46,14.65 71.93,10.18 71.93,8.55 75.18,8.55 76.61,7.13 76.61,2.25 76.81,2.05 LED2.K
  Bottom 0.254: v100.58,95.32 104.65,95.32 106.48,93.49 106.48,93.09 IC8.22
N$44
  Bottom 0.254: R41.1 119.48,1.85 119.69,2.05 122.53,2.05 LED1.A
N$45
  Top 0.254: LED2.A 74.37,2.05 74.78,2.46 74.78,5.1 R42.1
N$46
  Top 0.254: LED3.A 34.95,2.05 37.59,4.69 37.59,5.71 R43.1
N$47
  Bottom 0.254: LED4.A 29.26,2.05 33.12,5.91 34.14,5.91 R44.1
N$48
  Top 0.254: LED3.K 41.45,5.91 48.16,5.91 48.16,12.01 51.61,15.46 51.61,16.68 55.47,20.54 55.47,30.91 56.29,31.72 56.29,33.95 56.69,34.36 56.69,42.9 57.3,43.51 57.3,46.15 59.33,48.18 59.33,68.09 65.02,73.78 68.28,73.78 72.75,78.25 72.75,87.19 82.3,96.74 103.43,96.74 103.43,94.1 103.83,93.69 103.83,93.09 IC8.23
N$49  (via drill 0.51)
  Top 0.254: v48.97,9.98 49.17,10.18 49.17,11.6 52.22,14.65 52.22,16.28 59.13,23.18 59.13,27.86 59.94,28.67 59.94,33.14 62.79,35.99 62.79,46.76 61.77,47.77 61.77,62 66.24,66.47 66.24,69.51 67.46,70.73 67.46,71.55 68.07,72.16 71.53,72.16 71.53,75.41 75.18,79.06 75.18,80.69 90.63,96.13 101.4,96.13 101.4,93.09 IC8.24
  Bottom 0.254: v48.97,9.98 43.08,4.08 33.93,4.08 31.9,2.05 LED4.K
N$50
  Bottom 0.254: IC8.2 96.11,87.6 137.16,87.6 138.38,86.38 R49.1 139.6,86.38 145.9,92.68 JP11.1
N$51
  Top 0.254: JP10.1 142.24,92.68 139.19,89.63 139.19,89.02 R48.1
  Bottom 0.254: IC8.1 91.24,85.36 91.24,87.8 94.69,87.8 95.5,88.61 138.38,88.61 138.58,88.82 138.99,88.82 R48.1
N$52  (via drill 0.51)
  Top 0.254: v44.09,75.61 44.09,83.74 | 44.09,83.74 44.3,83.94 44.3,84.35 C18.1 | 44.09,83.74 44.09,89.02 45.72,90.65 R24.1
  Bottom 0.254: v44.09,75.61 44.3,75.61 49.38,70.53 C17.2
N$53  (via drill 0.51)
  Top 0.254: v92.86,89.02 91.64,90.24 91.64,92.68 91.44,92.88 IC8.28 | R47.1 138.99,83.94 137.36,85.57 137.36,90.65 138.38,91.66 138.38,92.68 JP9.1
  Bottom 0.254: v92.86,89.02 93.07,89.22 134.31,89.22 137.77,92.68 138.38,92.68 JP9.1
N$54
  Top 0.254: R46.1 138.99,82.11 134.72,86.38 134.72,92.68 JP8.1
  Bottom 0.254: IC8.27 93.88,93.09 96.93,96.13 130.45,96.13 133.71,92.88 134.52,92.88 JP8.1
N$55
  Top 0.254: JP3.2 37.8,38.83 38.41,38.22 38.41,34.16 49.58,34.16 49.99,33.75 49.99,33.35 50.8,32.53 R63.2
N$56
  Top 0.254: LED5.K 84.53,1.85 82.3,4.08 82.3,9.98 81.28,10.99 80.87,10.99 79.86,12.01 79.86,13.63 77.83,15.67 77.83,18.71 80.87,21.76 80.87,26.84 82.09,28.06 82.09,28.67 Q3.1
N$57
  Bottom 0.254: R55.1 80.67,1.65 81.69,1.65 81.89,1.85 LED5.A
N$58
  Top 0.254: C40.1 142.24,78.05 145.09,75.2 145.09,69.51 JP7.2
N$59  (via drill 0.51)
  Top 0.254: v82.5,35.38 82.5,32.33 80.87,30.7 Q3.2
  Bottom 0.254: v82.5,35.38 84.33,37.21 89.61,37.21 90.42,36.39 92.25,36.39 93.27,37.41 98.55,37.41 100.38,39.24 112.98,39.24 113.18,39.03 123.14,39.03 124.16,40.05 R11.1
N$60  (via drill 0.51)
  Top 0.254: v140.41,30.3 145.69,25.01 145.69,19.93 147.32,18.31 R52.1
  Bottom 0.254: v140.41,30.3 126.8,30.3 IC9.16 | J2.2 141.02,17.29 141.63,17.9 146.71,17.9 147.12,18.31 147.32,18.31 R52.1
N$61  (via drill 0.51)
  Top 0.254: IC9.12 122.33,19.93 122.33,16.48 v124.16,14.65
  Bottom 0.254: v124.16,14.65 127.61,14.65 130.05,17.09 133.1,17.09 | 133.1,17.09 133.3,17.09 J2.8 133.1,17.09 | 133.1,17.09 142.44,7.74 147.32,7.74 R54.1
N$62
  Bottom 0.254: IC9.13 124.56,20.34 126.8,18.11 131.88,18.11 133.1,19.32 133.91,19.32 134.11,19.53 134.52,19.53 J2.7 134.72,19.53 135.13,19.53 136.96,17.7 136.96,17.09 138.58,15.46 141.63,15.46 143.05,16.89 156.67,16.89 157.48,16.07 R53.2
N$63
  Top 0.254: IC9.27 96.52,27.86 97.54,26.84 97.54,26.44 99.77,24.2 99.77,22.57 100.58,21.76 100.58,19.12 102.41,17.29 113.79,17.29 113.79,15.26 122.73,6.32 123.75,6.32 R58.1
N$64
  Bottom 0.254: IC9.26 99.16,27.86 99.16,26.23 100.58,24.81 101.4,24.81 102.82,23.39 113.39,23.39 115.82,20.95 115.82,17.9 124.77,17.9 126.19,16.48 R56.1
N$65
  Top 0.254: IC9.14 130.45,23.79 130.45,26.64 130.66,26.84 130.66,27.25 R57.2
N$66
  Top 0.254: R52.2 157.48,18.51 157.28,18.71 157.28,20.75 157.48,20.95 R51.1
  Bottom 0.254: 152.2,24.4 152.6,24 154.63,24 | 152.2,24.4 148.74,27.86 C48.1 | 154.63,24 156.67,24 E1.1 | 152.2,24.4 147.73,19.93 146.51,19.93 145.09,18.51 140.82,18.51 139.8,19.53 J2.3 | 154.63,24 157.48,21.15 R51.1
N$67  (via drill 0.51)
  Top 0.254: v93.67,23.59 93.67,20.54 93.88,20.34 IC9.1
  Bottom 0.254: v93.67,23.59 90.42,26.84 90.22,26.84 88.39,28.67 C50.+
N$68
  Top 0.254: C52.1 107.49,34.77 107.49,33.14 106.27,31.92 X2.2 106.27,31.72 106.68,31.31 IC9.23
N$69
  Top 0.254: 104.44,32.13 104.24,32.33 104.24,34.77 C51.1 | 104.44,32.13 104.65,31.92 X2.1 104.44,32.13 | 104.44,32.13 104.44,28.27 IC9.24
N$70
  Top 0.254: C57.1 84.33,9.57 82.3,11.6 82.3,15.87 82.09,16.07 82.09,17.09 IC10.7
N$71  (via drill 0.51)
  Top 0.254: v78.44,20.54 78.44,21.97 77.22,23.18 77.22,24.4 IC10.14 | E3.1 97.13,16.07 94.08,16.07 C54.1
  Bottom 0.254: v78.44,20.54 78.64,20.34 88.59,20.34 91.24,17.7 92.25,17.7 93.88,16.07 C54.1
N$72
  Bottom 0.254: IC10.3 71.73,17.09 71.73,13.84 74.98,13.84 76.81,12.01 77.42,12.01 C56.1
N$73
  Bottom 0.254: C64.1 11.58,24.81 14.22,27.45 16.46,27.45 R62.1
N$74
  Top 0.254: C55.2 73.76,12.21 73.97,12.41 73.97,15.87 74.17,16.07 74.17,17.09 IC10.4
N$75
  Top 0.254: C58.1 81.28,9.57 79.25,11.6 79.25,13.03 76.81,15.46 76.81,17.09 IC10.5
N$76
  Top 0.254: C58.2 81.28,12.21 80.47,13.03 80.47,14.85 79.25,16.07 79.25,17.09 IC10.6
N$77
  Top 0.254: E2.2 107.9,15.87 105.05,13.03 105.05,10.99 J3.2
N$78
  Top 0.254: E3.2 104.65,15.87 102.41,13.63 102.41,10.99 J3.3
N$79
  Top 0.254: R60.1 29.46,14.24 27.43,14.24 27.43,17.09 30.07,19.73 30.07,23.39 30.89,24.2 30.89,24.61 C63.-
N$80  (via drill 0.51)
  Top 0.254: v75.79,15.26 75.79,22.78 75.39,23.18 75.39,23.59 74.37,24.61 IC10.15
  Bottom 0.254: C53.1 121.11,15.87 119.48,14.24 117.86,14.24 116.23,15.87 115.62,15.87 E2.1 115.42,15.87 114.81,15.87 113.18,14.24 76.81,14.24 v75.79,15.26
N$81
  Top 0.254: R61.2 12.6,15.26 12.6,20.34 11.38,21.56 11.38,22.17 C64.2
N$82
  Top 0.254: IC3.3 58.32,85.77 55.88,88.21 R27.2
  Bottom 0.254: C18.2 49.58,84.55 53.44,88.41 55.88,88.41 R27.2
N$83
  Top 0.254: J3.8 100.99,8.35 103.43,8.35 J3.7
N$84
  Top 0.254: R60.2 45.11,19.73 53.24,19.73 53.24,23.39 E6.2 53.44,23.59 53.44,26.64 C65.1
N$85
  Top 0.254: IC11.7 35.56,30.5 C67.1
  Bottom 0.254: 35.56,31.31 37.19,32.94 40.03,32.94 40.44,32.53 40.64,32.53 R63.1 | R64.2 5.89,22.98 10.97,28.06 14.83,28.06 16.26,29.48 24.59,29.48 26.21,31.11 28.45,31.11 C69.+ 28.65,31.31 30.28,32.94 33.93,32.94 35.56,31.31 | 35.56,31.31 C67.1
N$86
  Top 0.254: R59.1 28.65,16.07 31.29,18.71 31.29,19.53 C60.2 31.29,19.73 32.51,20.95 32.51,25.42 30.48,27.45 26.82,27.45 R62.2
  Bottom 0.254: R62.2 26.82,27.25 27.64,26.44 31.5,26.44 33.73,24.2 34.14,24.2 IC11.2
N$87
  Top 0.254: C17.1 54.66,70.53 58.32,74.19 58.32,75.41 IC3.7 58.52,75.61 58.52,78.05 IC3.6 58.32,78.05 55.88,80.49 R25.2
N$88
  Bottom 0.254: R25.1 45.72,80.49 47.35,80.49 47.35,76.42 49.38,74.39 C20.1 49.58,74.39 50.19,74.39 51.82,72.77 62.99,72.77 64.62,71.14 C19.2
N$89
  Top 0.254: C20.2 54.66,74.39 55.88,75.61 R28.2
  Bottom 0.254: IC3.5 58.32,80.49 55.88,78.05 R28.2
N$90
  Top 0.254: 66.04,75.61 64.21,75.61 59.74,71.14 C19.1 | 66.04,75.61 IC3.9 | 66.04,75.61 68.48,75.61 R26.2 | 66.04,75.61 IC3.8
N$91
  Bottom 0.254: 73.76,72.77 73.76,74.59 77.01,74.59 78.03,75.61 78.64,75.61 R26.1 | 73.76,72.77 73.76,71.14 C21.2 | 73.76,72.77 80.26,72.77 81.89,71.14 C22.1
N$92  (via drill 0.51)
  Top 0.254: IC3.10 66.04,80.69 68.48,80.69 68.48,78.86 R29.2 | v76.61,75.41 76.61,71.34 76.81,71.14 C22.2
  Bottom 0.254: v76.61,75.41 73.36,78.66 68.68,78.66 R29.2
N$93
  Bottom 0.254: E4.1 49.58,15.87 53.44,12.01 53.65,12.01 54.25,11.4 54.25,8.35 54.46,8.35 P1.7
N$94
  Bottom 0.254: E5.1 45.72,15.87 50.39,11.2 P1.1
N$95  (via drill 0.6)
  other vias: 13.61,66.47
N$96
  Top 0.254: E7.1 57.1,15.87 55.88,14.65 P1.3
N$97
  Top 0.254: E8.1 60.96,15.87 58.73,13.63 58.73,10.99 P1.4
N$98
  Top 0.254: E6.1 53.24,15.87 53.24,10.99 P1.2
N$99
  Top 0.254: R59.2 28.45,5.91 26.82,7.54 26.82,17.5 28.45,19.12 28.45,19.53 C60.1 28.45,19.73 28.45,24.4 C63.+
  Bottom 0.254: IC11.6 37.8,17.5 34.95,17.5 34.75,17.29 33.73,17.29 32.92,18.11 30.07,18.11 28.65,19.53 C60.1
N$100
  Top 0.254: 7.11,23.79 6.3,24.61 5.89,24.61 R65.2 | 7.11,23.79 7.32,23.59 7.32,14.24 5.89,12.82 R64.1 | IC11.3 33.12,22.78 33.12,25.62 29.46,29.28 17.27,29.28 17.27,31.11 C66.1 | 7.11,23.79 12.6,29.28 12.6,29.69 C68.+
  Bottom 0.254: C66.1 17.07,31.11 15.85,29.89 12.8,29.89 C68.+
N$101  (via drill 0.6)
  other vias: 17.07,66.47
N$102  (via drill 0.51)
  Top 0.635: v33.73,30.91 33.73,31.92 35.15,33.35 35.15,39.44 JP3.1 | C78.+ 134.11,41.88 v134.11,43.91 | v89,39.03 v92.05,42.08
  Bottom 0.635: C78.+ 137.77,38.22 139.4,38.22 | 139.4,38.22 VR1.3 | C73.1 137.77,33.95 139.4,35.58 139.4,38.22 | E9.1 16.66,17.9 16.66,21.56 C72.1 16.87,21.76 18.49,21.76 18.49,24.61 19.91,26.03 22.15,26.03 25.2,29.08 31.9,29.08 33.33,30.5 | 33.33,30.5 v33.73,30.91 | v134.11,43.91 112.78,43.91 110.95,42.08 v92.05,42.08 | v89,39.03 71.93,39.03 64.01,31.11 42.06,31.11 40.23,29.28 34.54,29.28 33.33,30.5
N$103  (via drill 0.51)
  Top 0.254: v83.92,19.53 87.99,23.59 87.99,26.84 86.56,28.27 86.56,31.52 86.77,31.72 86.77,33.95 85.14,35.58 R67.2
  Bottom 0.254: C76.1 E10.1 20.32,17.7 20.93,17.7 24.38,14.24 41.66,14.24 46.94,19.53 v83.92,19.53
N$104
  Top 0.254: E11.2 23.98,10.18 23.98,3.88 J4.5
N$105  (via drill 0.51)
  Top 0.254: C77.1 23.98,21.56 23.98,17.9 E11.1 | v93.67,35.38 91.44,33.14 v91.44,32.13
  Bottom 0.254: v91.44,32.13 91.24,31.92 81.89,31.92 81.48,32.33 78.23,32.33 75.39,29.48 74.37,29.48 73.56,30.3 66.04,30.3 60.96,25.22 37.8,25.22 35.56,22.98 26.21,22.98 24.79,21.56 24.18,21.56 C77.1 | v93.67,35.38 R69.2
N$107
  Top 0.254: E10.2 21.54,8.96 21.54,3.88 J4.4
N$108
  Top 0.254: CR6.A 85.34,44.32 86.16,45.13 86.16,60.57 84.53,62.2 84.53,81.5 87.38,84.35 87.38,84.55 R45.1
  Bottom 0.254: IC8.25 98.75,92.88 95.71,89.83 92.46,89.83 87.38,84.75 R45.1
N$109  (via drill 0.51)
  Top 0.254: v31.29,90.85 26.21,85.77 IC14.4
  Bottom 0.254: v31.29,90.85 43.28,90.85 44.91,92.48 73.56,92.48 78.23,87.8 78.64,87.8 R30.1
N$110  (via drill 0.6)
  other vias: 13.61,63.62
N$114  (via drill 0.51)
  Top 0.254: v36.98,76.63 29.06,84.55 29.06,85.36 28.85,85.57 IC14.5 | v73.56,69.72 74.98,68.3 74.98,52.65 76.81,50.82 77.22,50.82 | 77.22,50.82 IC4.8 77.42,50.82 | 77.22,50.82 77.22,49.4 74.37,46.55 C31.2
  Bottom 0.254: v36.98,76.63 44.3,76.63 48.77,72.16 56.29,72.16 58.93,69.51 73.36,69.51 v73.56,69.72 | R37.2 79.86,51.43 79.25,50.82 IC4.8
NVOLT  (via drill 0.51)
  Top 0.254: v23.98,83.13 22.55,81.71 22.55,72.97 22.35,72.77 22.35,69.51 19.71,66.87 R18.2 | v91.24,77.03 97.74,70.53 97.74,70.12 100.99,66.87 v102.41,66.87 | v106.07,66.87 107.09,65.86 107.09,63.83 IC6.4
  Bottom 0.254: v23.98,83.13 24.18,82.93 48.77,82.93 49.38,82.32 56.29,82.32 56.9,81.71 61.98,81.71 64.01,79.67 67.26,79.67 68.07,80.49 87.38,80.49 90.83,77.03 v91.24,77.03 | v102.41,66.87 v106.07,66.87
PTT
  Top 0.254: C61.1 49.38,26.64 49.38,23.59 E4.2
  Bottom 0.254: Q1.1 76.2,28.47 74.57,26.84 72.75,26.84 72.34,27.25 70.31,27.25 69.9,26.84 63.4,26.84 61.16,24.61 51.21,24.61 50.19,23.59 49.58,23.59 E4.2
RXAUDIO  (via drill 0.51)
  Top 0.254: IC4.2 69.9,63.62 69.9,66.06 IC4.1 | v91.64,69.11 91.64,67.28 98.55,67.28 102.01,63.83 IC6.2
  Bottom 0.254: v91.64,69.11 91.44,68.91 90.83,68.91 89.61,67.69 72.14,67.69 70.51,66.06 IC4.1 63.6,66.06 62.38,64.84 C25.2
RXFLAT  (via drill 0.51)
  Top 0.254: IC14.15 21.13,93.09 21.13,88.61 22.55,87.19 22.55,86.79 23.57,85.77 IC14.3 23.77,85.57 23.77,84.75 24.79,83.74 24.79,83.13 27.43,83.13 39.22,71.34 39.22,70.94 41.66,68.5 41.66,65.65 v41.86,65.45
  Bottom 0.254: v41.86,65.45 43.69,65.45 46.13,63.01 54.25,63.01 57.3,59.96 71.32,59.96 71.53,59.76 72.95,59.76 75.79,56.92 79.86,56.92 79.86,54.68 R38.1
RXIN  (via drill 0.51)
  Top 0.254: E7.2 57.3,23.59 57.3,26.64 C70.1 57.3,26.84 57.3,27.05 58.93,28.67 58.93,31.92 57.91,32.94 C10.2 | v54.25,33.95 50.6,37.61 50.6,54.68 48.36,54.68 R35.3
  Bottom 0.254: v54.25,33.95 54.46,34.16 56.49,34.16 57.51,33.14 57.71,33.14 C10.2
SCK  (via drill 0.51)
  Top 0.254: v52.43,20.54 46.33,20.54 44.09,22.78 44.09,22.98 40.44,22.98 32.92,30.5 32.92,32.94 30.89,32.94 27.64,36.19 27.64,38.43 IC1.2 | v88.59,68.5 85.14,65.04 85.14,62.61 87.17,60.57 87.17,43.51 87.38,43.3 87.38,34.16 90.02,31.52 v90.02,26.03
  Bottom 0.254: 91.44,69.92 91.44,71.14 IC7.6 | 91.44,69.92 92.05,69.92 93.07,68.91 125.78,68.91 127.41,70.53 127.41,71.14 IC6.17 127.41,71.34 127.41,71.95 125.17,74.19 123.14,74.19 123.14,81.3 119.28,85.16 IC8.12 | v52.43,20.54 52.63,20.75 77.42,20.75 78.03,21.36 91.85,21.36 93.27,22.78 | 93.27,22.78 109.93,22.78 111.76,20.95 IC9.8 | 91.44,69.92 91.03,69.92 89.61,68.5 v88.59,68.5 | 93.27,22.78 v90.02,26.03
SDI  (via drill 0.51)
  Top 0.254: v122.73,83.13 122.73,77.44 117.65,72.36 117.65,71.55 117.45,71.34 IC6.21 117.25,71.14 v117.25,68.09 | v89.61,20.54 88.59,21.56 88.59,23.39 90.83,25.62 90.83,31.52 87.99,34.36 v87.99,60.17
  Bottom 0.254: v122.73,83.13 124.16,84.55 124.16,85.16 IC8.14 | IC9.6 106.68,17.9 92.86,17.9 90.22,20.54 v89.61,20.54 | v87.99,60.17 87.99,62.81 88.8,63.62 IC7.2 88.8,63.83 88.8,64.84 91.24,67.28 94.49,67.28 95.5,68.3 117.04,68.3 v117.25,68.09
SDO  (via drill 0.51)
  Top 0.254: v107.7,31.52 107.7,23.59 108.92,22.37 108.92,20.54 109.12,20.34 IC9.7 | v115.42,35.38 119.08,39.03 119.08,59.96 121.31,62.2 121.31,67.08 124.77,70.53 124.77,71.14 IC6.18 124.97,71.34 124.97,72.36 126.59,73.98 126.59,82.93 124.16,82.93 121.92,85.16 IC8.13 | v26.21,45.33 26.42,45.54 26.42,66.26 v28.65,68.5 | v67.87,67.69 73.76,73.58 v74.98,73.58
  Bottom 0.254: v107.7,31.52 108.92,32.74 109.12,32.74 111.76,35.38 v115.42,35.38 | v26.21,45.33 22.35,41.47 IC1.3 | v28.65,68.5 28.85,68.3 32.92,68.3 34.95,66.26 49.78,66.26 51.21,67.69 v67.87,67.69 | v74.98,73.58 84.12,73.58 86.16,75.61 90.22,75.61 93.67,72.16 93.67,71.55 | 93.67,71.55 93.67,71.34 IC7.5 93.67,71.55 | 93.67,71.55 95.1,71.55 97.33,73.78 122.53,73.78 122.73,73.58 124.97,73.58 124.97,71.34 IC6.18
SER_RX  (via drill 0.51)
  Top 0.254: v82.7,54.27 82.7,38.22 77.83,33.35 77.83,28.06 79.05,26.84 79.05,25.01 79.25,24.81 IC10.13 | v111.96,67.48 112.17,67.69 112.17,71.14 IC6.23
  Bottom 0.254: v82.7,54.27 87.78,59.35 88.39,59.35 90.22,61.18 90.22,65.45 91.44,66.67 100.58,66.67 101.6,67.69 111.76,67.69 v111.96,67.48
SER_TX  (via drill 0.51)
  Top 0.254: v83.72,74.39 83.72,70.53 80.87,67.69 80.87,58.34 83.52,55.7 83.52,53.87 83.31,53.67 83.31,32.33 83.92,31.72 83.92,27.45 82.3,25.83 82.3,25.01 82.09,24.81 IC10.12 | v110.54,76.22 114.61,72.16 114.61,71.34 IC6.22
  Bottom 0.254: v83.72,74.39 85.55,76.22 v110.54,76.22
SQLC  (via drill 0.51)
  Top 0.254: v107.09,59.35 109.73,62 109.73,63.62 IC6.5
  Bottom 0.254: v107.09,59.35 105.05,57.32 96.32,57.32 92.05,53.05 87.38,53.05 83.52,49.19 74.78,49.19 70.31,44.72 68.48,44.72 67.06,46.15 64.01,46.15 59.94,42.08 50.19,42.08 49.78,41.68 49.38,41.68 48.36,40.66 R22.2
VCC  (via drill 0.51)
  Top 0.635: R44.2 34.34,15.87 37.39,15.87 R43.2 | IC10.17 69.09,24.81 66.85,24.81 IC10.18 66.85,25.01 66.85,28.47 C59.1 | R42.2 85.14,5.1 85.34,5.3 85.34,7.13 R55.2 85.95,8.15 85.95,10.79 86.36,11.2 86.36,13.23 92.05,18.92 92.05,22.17 | IC9.25 101.6,28.06 101.4,28.27 101.4,28.87 99.16,31.11 99.16,31.72 C46.1 | 92.05,22.17 92.05,26.23 93.67,27.86 IC9.28 94.69,28.67 94.69,29.69 95.71,30.7 95.71,31.72 C47.1 95.71,32.13 94.69,33.14 94.69,49.19 96.72,51.23 96.72,54.68 IC5.16 96.72,54.88 96.72,58.34 C42.1 | R41.2 119.28,12.01 116.84,14.45 116.84,17.29 115.62,18.51 115.62,22.37 116.64,23.39 116.64,27.66 116.84,27.86 IC9.19 116.64,28.06 116.64,31.31 116.23,31.72 C44.1 | C43.1 124.56,31.72 127,29.28 IC9.15 | v91.44,22.17 92.05,22.17 | R48.2 149.35,88.82 149.56,88.61 149.56,86.58 R49.2 149.35,86.38 149.56,86.18 149.56,83.94 R47.2 149.35,83.74 149.56,83.53 149.56,81.91 R46.2 149.15,81.91 149.15,81.71 148.95,81.5 148.95,79.67 148.74,79.47 148.74,78.86 148.13,78.25 C34.1 147.93,77.85 150.77,75 150.77,63.62 v150.98,63.42 142.85,55.29 142.85,54.07 VR2.3 | C35.1 129.84,61.79 129.84,63.62 IC6.13 | C41.1 111.76,81.5 111.76,85.16 IC8.9 | C38.1 91.24,78.86 87.78,75.41 87.78,74.59 R45.2 87.58,74.39 88.59,73.38 88.59,71.34 IC7.7 88.59,71.14 88.59,69.92 89.61,68.91 89.61,68.3 91.44,66.47 91.44,63.83 IC7.3
  Bottom 0.635: R43.2 37.59,16.07 38.61,17.09 43.48,17.09 47.95,21.56 62.18,21.56 65.43,24.81 66.65,24.81 IC10.18 | R10.2 85.75,33.55 92.25,33.55 92.46,33.75 94.08,33.75 95.91,31.92 C47.1 96.11,32.13 98.75,32.13 98.96,31.92 C46.1 | 114.61,32.94 115.82,31.72 116.03,31.72 C44.1 | 114.61,32.94 113.79,33.75 112.37,33.75 110.54,31.92 C45.1 110.34,31.52 109.73,31.52 108.71,30.5 104.04,30.5 101.6,28.06 IC9.25 | IC9.20 114.4,28.06 116.84,28.06 IC9.19 | E1.2 149.15,24.2 144.07,29.28 129.64,29.28 128.42,28.06 127,28.06 IC9.15 | 114.61,32.94 115.42,33.75 122.73,33.75 124.56,31.92 C43.1 | v91.44,22.17 69.09,22.17 69.09,24.61 IC10.17 | R39.2 155.45,86.99 152.6,84.14 149.76,84.14 149.56,83.94 149.35,83.94 R47.2 | 140,51.84 142.24,54.07 VR2.3 | 140,51.84 137.77,49.6 C74.1 | 140,51.84 139.8,52.04 139.6,52.04 C79.+ 133.71,57.93 | v150.98,63.42 155.45,63.42 J1.2 | 133.71,57.93 C35.1 | R19.1 36.37,71.14 37.19,70.33 37.59,70.33 38,69.92 44.91,69.92 46.13,68.7 82.3,68.7 84.94,71.34 86.16,71.34 IC7.8 86.36,71.34 88.59,71.34 IC7.7 | IC7.3 91.44,63.62 91.44,58.75 96.11,58.75 96.32,58.54 96.52,58.54 C42.1 96.52,58.75 98.15,60.37 99.97,60.37 100.18,60.17 102.82,60.17 103.02,60.37 108.51,60.37 109.53,59.35 C33.1 109.53,58.95 111.15,57.32 133.1,57.32 133.71,57.93 | C41.1 111.56,81.3 107.29,77.03 93.67,77.03 91.85,78.86 91.44,78.86 C38.1
VF  (via drill 0.51)
  Top 0.254: v14.83,75.81 15.04,75.61 15.04,49.6 16.87,47.77 16.87,43.91 18.09,42.69 20.12,42.69 20.12,39.64 19.91,39.44 19.91,38.02 24.59,33.35 24.59,31.31 C14.1 | v106.07,78.05 106.07,77.85 111.15,72.77 111.15,66.26 111.76,65.65 111.76,64.23 112.17,63.83 IC6.6
  Bottom 0.254: C14.1 24.79,31.31 29.06,35.58 R20.1 | v14.83,75.81 16.46,77.44 | 16.46,77.44 16.87,77.85 18.09,77.85 18.29,78.05 CR5.A | v106.07,78.05 105.87,77.85 97.33,77.85 92.66,82.52 90.83,82.52 90.63,82.32 81.48,82.32 71.93,91.87 45.31,91.87 42.06,88.61 18.49,88.61 16.05,86.18 16.05,77.44 16.46,77.44
VIN  (via drill 0.51)
  Top 0.635: E5.2 C62.1 45.92,26.44 47.55,28.06 47.55,31.72 v47.95,32.13 | v70.1,40.66 68.89,39.44 v68.89,38.63
  Bottom 0.635: D1.A 138.79,42.9 112.98,42.9 111.15,41.07 70.51,41.07 v70.1,40.66 | v68.89,38.63 59.74,38.63 56.08,34.97 50.8,34.97 v47.95,32.13
VIN-RECT
  Top 0.635: 150.98,54.07 153.01,54.07 C80.+ | 150.98,54.07 VR2.1 | C75.+ 152.81,38.43 147.93,38.43 147.93,38.22 VR1.1 | D1.C 150.98,45.33 150.98,54.07
  Bottom 0.635: 146.51,40.66 147.73,39.44 147.73,38.22 VR1.1 | 146.51,40.66 145.29,41.88 113.79,41.88 111.96,40.05 71.73,40.05 71.32,39.64 59.54,39.64 56.08,36.19 46.74,36.19 44.91,38.02 41.86,38.02 40.44,39.44 JP3.3 | D1.C 146.91,40.86 146.71,40.86 146.51,40.66
VREF3.3
  Top 0.254: C16.+ 64.41,37 64.41,41.68 64.62,41.88 C15.1 64.82,42.08 66.85,44.11 66.85,55.09 C24.1 | R29.1 80.47,77.03 80.47,72.16 79.86,71.55 79.86,57.53 78.23,55.9 IC4.10 | R27.1 45.72,87.6 47.35,85.97 47.35,79.27 45.72,77.64 R28.1 45.72,77.44 44.91,76.63 44.91,72.16 44.7,71.95 44.7,66.47 42.67,64.43 42.67,64.23 R7.1 42.67,64.03 42.67,63.83 44.3,62.2 44.3,55.7 42.67,54.07 R6.1 | R9.1 9.35,54.07 9.35,56.51 R8.1
  Bottom 0.254: 60.76,35.78 58.73,35.78 58.52,35.58 R21.1 | 60.76,35.78 63.2,35.78 64.21,36.8 C16.+ | 60.76,35.78 R23.2 | IC4.10 IC4.5 68.89,55.9 68.48,56.31 67.87,56.31 66.85,55.29 C24.1 65.63,56.31 45.31,56.31 43.08,54.07 42.67,54.07 R6.1 42.47,53.87 42.27,53.87 38.81,50.41 25.2,50.41 24.59,49.8 7.92,49.8 7.92,52.45 9.35,53.87 R9.1

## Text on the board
tValues: 1
Name: VOTER BOARD REV. A JIM DIXON WB6NIL 03/08/2011 | DUUUUDE!!! | PICAGE | ROMAGE | LIKE | WOW | TO THE MAX! | TOTALLY!!!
